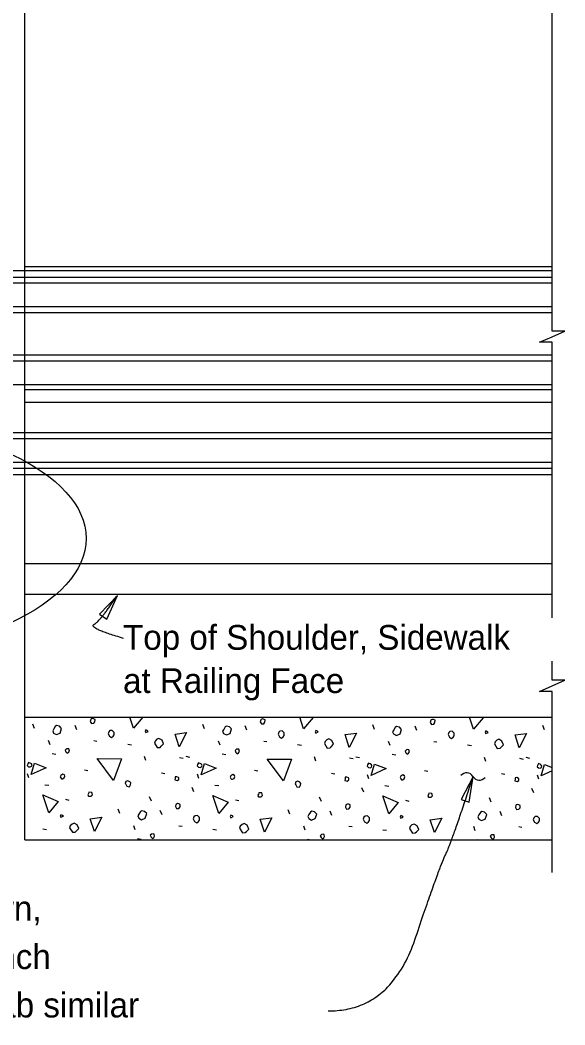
# Model space of a CAD drawing. Extents: x 120631.6 to 120706.2, y 120663.5 to 120716.4.
# Drawn here: x 120670.21 to 120674.64, y 120691.04 to 120699.22 of the extents above; entities that cross this region are included whole.
import ezdxf

# ---------------------------------------------------------------- set-up
doc = ezdxf.new("R2010")
doc.units = 0
for name, color, linetype in [('Dimension', 7, 'Continuous'), ('Miscellaneous', 7, 'Continuous'), ('SteelMisc_h', 7, 'Continuous'), ('TextStructures', 7, 'Continuous'), ('TrafBarrierConc', 7, 'Continuous')]:
    doc.layers.add(name, color=color, linetype=linetype)

msp = doc.modelspace()

# ---------------------------------------------------------------- linework, layer by layer
at = {"layer": 'Dimension'}
for points in [[(120674.5392, 120697.2127), (120674.5392, 120699.4757), (120674.4358, 120699.4757), (120674.5392, 120699.5207), (120674.6425, 120699.5657), (120674.5392, 120699.5657), (120674.5392, 120702.646)], [(120674.5392, 120695.9808), (120674.5392, 120696.597), (120674.4358, 120696.597), (120674.5392, 120696.642), (120674.6425, 120696.687), (120674.5392, 120696.687), (120674.5392, 120697.2127)], [(120674.5392, 120694.354), (120674.5392, 120695.9808)], [(120674.5392, 120692.2813), (120674.5392, 120693.7558), (120674.4358, 120693.7558), (120674.5392, 120693.8008), (120674.6425, 120693.8458), (120674.5392, 120693.8458), (120674.5392, 120694.0007)]]:
    msp.add_lwpolyline(points, dxfattribs=at)
for points in [[(120671.0028, 120694.5372), (120670.8585, 120694.383), (120670.9174, 120694.3441)], [(120673.8957, 120693.0627), (120673.7981, 120692.8754), (120673.8652, 120692.8537)]]:
    msp.add_lwpolyline(points, close=True, dxfattribs=at)
for centre, start, end in [((120673.8434, 120693.033), 30.00813, 141.73535), ((120673.9466, 120693.0926), 210.00813, 321.73535)]:
    msp.add_arc(centre, 0.0596, start, end, dxfattribs=at)
msp.add_ellipse((120668.6608, 120695.0005), major_axis=(2.0883, 0), ratio=0.464675, dxfattribs=at)
for points in [[(120671.0528, 120694.1873), (120670.7621, 120694.2707), (120670.8662, 120694.3306), (120671.0028, 120694.5372)], [(120672.7165, 120691.155), (120673.2263, 120691.1516), (120673.6239, 120692.3306), (120673.7232, 120692.5293), (120673.8957, 120693.0627)]]:
    msp.add_open_spline(points, degree=2, dxfattribs=at)
at = {"layer": 'Miscellaneous'}
for p, q in [((120670.3302, 120693.4537), (120670.3161, 120693.4891)), ((120671.7126, 120693.4502), (120671.6985, 120693.4855)), ((120673.095, 120693.4466), (120673.0809, 120693.482)), ((120670.6732, 120693.4431), (120670.659, 120693.4784)), ((120672.0556, 120693.4396), (120672.0414, 120693.4749)), ((120673.438, 120693.436), (120673.4238, 120693.4714)), ((120674.4774, 120693.4431), (120674.4633, 120693.4784)), ((120670.4557, 120693.3211), (120670.4434, 120693.3547)), ((120670.8111, 120693.3547), (120670.8358, 120693.3512)), ((120671.0868, 120693.3264), (120671.1169, 120693.3211)), ((120671.8381, 120693.3176), (120671.8258, 120693.3512)), ((120672.1934, 120693.3512), (120672.2182, 120693.3476)), ((120672.4692, 120693.3229), (120672.4993, 120693.3176)), ((120673.2205, 120693.314), (120673.2081, 120693.3476)), ((120673.5758, 120693.3476), (120673.6006, 120693.3441)), ((120673.8516, 120693.3194), (120673.8817, 120693.314)), ((120670.4734, 120693.2504), (120670.5035, 120693.2451)), ((120671.8558, 120693.2469), (120671.8859, 120693.2416)), ((120673.2382, 120693.2433), (120673.2683, 120693.238)), ((120671.2353, 120693.1921), (120671.2229, 120693.2257)), ((120671.5093, 120693.2186), (120671.5376, 120693.2115)), ((120671.5606, 120693.2274), (120671.5889, 120693.2204)), ((120672.6177, 120693.1885), (120672.6053, 120693.2221)), ((120672.8917, 120693.2151), (120672.92, 120693.208)), ((120672.943, 120693.2239), (120672.9713, 120693.2168)), ((120674.0001, 120693.185), (120673.9877, 120693.2186)), ((120674.2741, 120693.2115), (120674.3024, 120693.2044)), ((120674.3254, 120693.2204), (120674.3537, 120693.2133)), ((120670.2843, 120693.0507), (120670.2719, 120693.0842)), ((120670.7368, 120693.1178), (120670.7633, 120693.1125)), ((120671.3626, 120693.0931), (120671.3891, 120693.0878)), ((120671.6667, 120693.0471), (120671.6543, 120693.0807)), ((120672.1192, 120693.1143), (120672.1457, 120693.109)), ((120672.745, 120693.0895), (120672.7715, 120693.0842)), ((120673.049, 120693.0436), (120673.0367, 120693.0772)), ((120673.5016, 120693.1108), (120673.5281, 120693.1055)), ((120674.1274, 120693.086), (120674.1539, 120693.0807)), ((120674.4314, 120693.04), (120674.4191, 120693.0736)), ((120670.4133, 120692.9958), (120670.4451, 120692.9923)), ((120671.7957, 120692.9923), (120671.8275, 120692.9888)), ((120671.6242, 120692.9375), (120671.6101, 120692.9729)), ((120673.0066, 120692.934), (120672.9925, 120692.9693)), ((120673.1781, 120692.9888), (120673.2099, 120692.9852)), ((120674.389, 120692.9304), (120674.3749, 120692.9658)), ((120670.5812, 120692.8774), (120670.6095, 120692.8703)), ((120671.2795, 120692.8615), (120671.2654, 120692.8969)), ((120671.9636, 120692.8739), (120671.9919, 120692.8668)), ((120672.6619, 120692.858), (120672.6478, 120692.8933)), ((120673.346, 120692.8703), (120673.3743, 120692.8633)), ((120674.0443, 120692.8544), (120674.0302, 120692.8898)), ((120671.0232, 120692.7607), (120671.009, 120692.7961)), ((120671.3661, 120692.7501), (120671.352, 120692.7855)), ((120672.4056, 120692.7572), (120672.3914, 120692.7926)), ((120672.7485, 120692.7466), (120672.7344, 120692.7819)), ((120674.1309, 120692.7431), (120674.1168, 120692.7784)), ((120670.3974, 120692.637), (120670.4274, 120692.6317)), ((120671.1487, 120692.6282), (120671.1363, 120692.6617)), ((120671.504, 120692.6617), (120671.5288, 120692.6582)), ((120671.7798, 120692.6335), (120671.8098, 120692.6282)), ((120672.5311, 120692.6246), (120672.5187, 120692.6582)), ((120672.8864, 120692.6582), (120672.9112, 120692.6547)), ((120673.1622, 120692.6299), (120673.1922, 120692.6246)), ((120673.9135, 120692.6211), (120673.9011, 120692.6547)), ((120674.2688, 120692.6547), (120674.2936, 120692.6511)), ((120671.1664, 120692.5574), (120671.1964, 120692.5521)), ((120672.5488, 120692.5539), (120672.5788, 120692.5486)), ((120673.9312, 120692.5504), (120673.9558, 120692.546))]:
    msp.add_line(p, q, dxfattribs=at)
for points in [[(120670.7828, 120693.5103), (120670.7916, 120693.4944), (120670.8111, 120693.4961), (120670.8199, 120693.5085), (120670.8217, 120693.5279), (120670.8093, 120693.5333), (120670.8004, 120693.535), (120670.7898, 120693.5315), (120670.7863, 120693.5279), (120670.7828, 120693.5103)], [(120671.1346, 120693.4555), (120671.1051, 120693.546)], [(120671.2112, 120693.546), (120671.1346, 120693.4555)], [(120672.1652, 120693.5067), (120672.174, 120693.4908), (120672.1934, 120693.4926), (120672.2023, 120693.505), (120672.2041, 120693.5244), (120672.1917, 120693.5297), (120672.1828, 120693.5315), (120672.1722, 120693.5279), (120672.1687, 120693.5244), (120672.1652, 120693.5067)], [(120672.517, 120693.4519), (120672.4863, 120693.546)], [(120672.5898, 120693.546), (120672.5947, 120693.5439), (120672.517, 120693.4519)], [(120673.5476, 120693.5032), (120673.5564, 120693.4873), (120673.5758, 120693.4891), (120673.5847, 120693.5014), (120673.5864, 120693.5209), (120673.5741, 120693.5262), (120673.5652, 120693.5279), (120673.5546, 120693.5244), (120673.5511, 120693.5209), (120673.5476, 120693.5032)], [(120673.8993, 120693.4484), (120673.8676, 120693.546)], [(120673.9641, 120693.546), (120673.9771, 120693.5403), (120673.8993, 120693.4484)], [(120670.484, 120693.4166), (120670.507, 120693.4042), (120670.5371, 120693.4166), (120670.5494, 120693.4537), (120670.5317, 120693.4714), (120670.5088, 120693.4767), (120670.4982, 120693.4696), (120670.4858, 120693.4502), (120670.4769, 120693.4343), (120670.484, 120693.4166)], [(120670.9277, 120693.4113), (120670.9383, 120693.3901), (120670.956, 120693.3795), (120670.9702, 120693.3901), (120670.9772, 120693.4007), (120670.9772, 120693.4219), (120670.9613, 120693.4378), (120670.9419, 120693.436), (120670.933, 120693.4272), (120670.9277, 120693.4113)], [(120671.2336, 120693.4201), (120671.253, 120693.429), (120671.2459, 120693.436), (120671.2336, 120693.4413), (120671.2282, 120693.429), (120671.2336, 120693.4201)], [(120671.5058, 120693.3034), (120671.4722, 120693.4077), (120671.5659, 120693.4201), (120671.5058, 120693.3034)], [(120671.8664, 120693.413), (120671.8894, 120693.4007), (120671.9194, 120693.413), (120671.9318, 120693.4502), (120671.9141, 120693.4678), (120671.8912, 120693.4731), (120671.8806, 120693.4661), (120671.8682, 120693.4466), (120671.8593, 120693.4307), (120671.8664, 120693.413)], [(120672.3101, 120693.4077), (120672.3207, 120693.3865), (120672.3384, 120693.3759), (120672.3525, 120693.3865), (120672.3596, 120693.3971), (120672.3596, 120693.4183), (120672.3437, 120693.4343), (120672.3243, 120693.4325), (120672.3154, 120693.4236), (120672.3101, 120693.4077)], [(120672.6159, 120693.4166), (120672.6354, 120693.4254), (120672.6283, 120693.4325), (120672.6159, 120693.4378), (120672.6106, 120693.4254), (120672.6159, 120693.4166)], [(120672.8882, 120693.2999), (120672.8546, 120693.4042), (120672.9483, 120693.4166), (120672.8882, 120693.2999)], [(120673.2488, 120693.4095), (120673.2718, 120693.3971), (120673.3018, 120693.4095), (120673.3142, 120693.4466), (120673.2965, 120693.4643), (120673.2736, 120693.4696), (120673.2629, 120693.4625), (120673.2506, 120693.4431), (120673.2417, 120693.4272), (120673.2488, 120693.4095)], [(120673.6925, 120693.4042), (120673.7031, 120693.383), (120673.7208, 120693.3724), (120673.7349, 120693.383), (120673.742, 120693.3936), (120673.742, 120693.4148), (120673.7261, 120693.4307), (120673.7067, 120693.429), (120673.6978, 120693.4201), (120673.6925, 120693.4042)], [(120673.9983, 120693.413), (120674.0178, 120693.4219), (120674.0107, 120693.429), (120673.9983, 120693.4343), (120673.993, 120693.4219), (120673.9983, 120693.413)], [(120674.2706, 120693.2964), (120674.237, 120693.4007), (120674.3307, 120693.413), (120674.2706, 120693.2964)], [(120671.3043, 120693.3353), (120671.3272, 120693.2981), (120671.3502, 120693.2999), (120671.3591, 120693.3087), (120671.3785, 120693.3282), (120671.3661, 120693.3582), (120671.3414, 120693.3724), (120671.3237, 120693.3653), (120671.3096, 120693.3512), (120671.3043, 120693.3353)], [(120672.6867, 120693.3317), (120672.7096, 120693.2946), (120672.7326, 120693.2964), (120672.7415, 120693.3052), (120672.7609, 120693.3247), (120672.7485, 120693.3547), (120672.7238, 120693.3688), (120672.7061, 120693.3618), (120672.692, 120693.3476), (120672.6867, 120693.3317)], [(120674.069, 120693.3282), (120674.092, 120693.2911), (120674.115, 120693.2928), (120674.1239, 120693.3017), (120674.1433, 120693.3211), (120674.1309, 120693.3512), (120674.1062, 120693.3653), (120674.0885, 120693.3582), (120674.0744, 120693.3441), (120674.069, 120693.3282)], [(120670.5848, 120693.2628), (120670.5954, 120693.2522), (120670.606, 120693.2592), (120670.6131, 120693.2699), (120670.6095, 120693.2875), (120670.6007, 120693.2893), (120670.5883, 120693.2875), (120670.5777, 120693.2769), (120670.5848, 120693.2628)], [(120671.9672, 120693.2592), (120671.9778, 120693.2486), (120671.9884, 120693.2557), (120671.9955, 120693.2663), (120671.9919, 120693.284), (120671.9831, 120693.2858), (120671.9707, 120693.284), (120671.9601, 120693.2734), (120671.9672, 120693.2592)], [(120673.3496, 120693.2557), (120673.3602, 120693.2451), (120673.3708, 120693.2522), (120673.3779, 120693.2628), (120673.3743, 120693.2805), (120673.3655, 120693.2822), (120673.3531, 120693.2805), (120673.3425, 120693.2699), (120673.3496, 120693.2557)], [(120670.2807, 120693.1426), (120670.2931, 120693.1408), (120670.3055, 120693.1461), (120670.309, 120693.1567), (120670.3037, 120693.1656), (120670.2931, 120693.1726), (120670.2807, 120693.1779), (120670.2737, 120693.1638), (120670.2701, 120693.1532), (120670.2807, 120693.1426)], [(120670.3019, 120693.0789), (120670.3302, 120693.1709), (120670.4239, 120693.1337), (120670.3019, 120693.0789)], [(120670.9719, 120693.0312), (120670.8376, 120693.208), (120671.0373, 120693.2062), (120670.9719, 120693.0312)], [(120671.6631, 120693.139), (120671.6755, 120693.1373), (120671.6879, 120693.1426), (120671.6914, 120693.1532), (120671.6861, 120693.162), (120671.6755, 120693.1691), (120671.6631, 120693.1744), (120671.656, 120693.1603), (120671.6525, 120693.1496), (120671.6631, 120693.139)], [(120671.6843, 120693.0754), (120671.7126, 120693.1673), (120671.8063, 120693.1302), (120671.6843, 120693.0754)], [(120672.3543, 120693.0277), (120672.22, 120693.2044), (120672.4197, 120693.2027), (120672.3543, 120693.0277)], [(120673.0455, 120693.1355), (120673.0579, 120693.1337), (120673.0703, 120693.139), (120673.0738, 120693.1496), (120673.0685, 120693.1585), (120673.0579, 120693.1656), (120673.0455, 120693.1709), (120673.0384, 120693.1567), (120673.0349, 120693.1461), (120673.0455, 120693.1355)], [(120673.0667, 120693.0719), (120673.095, 120693.1638), (120673.1887, 120693.1267), (120673.0667, 120693.0719)], [(120674.4279, 120693.132), (120674.4403, 120693.1302), (120674.4527, 120693.1355), (120674.4562, 120693.1461), (120674.4509, 120693.1549), (120674.4403, 120693.162), (120674.4279, 120693.1673), (120674.4208, 120693.1532), (120674.4173, 120693.1426), (120674.4279, 120693.132)], [(120674.4491, 120693.0683), (120674.4774, 120693.1603), (120674.5392, 120693.1358)], [(120670.5494, 120693.0436), (120670.5565, 120693.0436), (120670.5706, 120693.0507), (120670.5759, 120693.0666), (120670.5742, 120693.0754), (120670.56, 120693.0825), (120670.5424, 120693.0719), (120670.5388, 120693.0613), (120670.5424, 120693.0507), (120670.5494, 120693.0436)], [(120671.9318, 120693.04), (120671.9389, 120693.04), (120671.953, 120693.0471), (120671.9583, 120693.063), (120671.9566, 120693.0719), (120671.9424, 120693.0789), (120671.9247, 120693.0683), (120671.9212, 120693.0577), (120671.9247, 120693.0471), (120671.9318, 120693.04)], [(120673.3142, 120693.0365), (120673.3213, 120693.0365), (120673.3354, 120693.0436), (120673.3407, 120693.0595), (120673.339, 120693.0683), (120673.3248, 120693.0754), (120673.3071, 120693.0648), (120673.3036, 120693.0542), (120673.3071, 120693.0436), (120673.3142, 120693.0365)], [(120674.5392, 120693.1088), (120674.4491, 120693.0683)], [(120671.0709, 120692.9994), (120671.0798, 120692.9835), (120671.101, 120692.9799), (120671.1098, 120692.9958), (120671.1133, 120693.01), (120671.1045, 120693.0188), (120671.0886, 120693.0277), (120671.0727, 120693.0224), (120671.0674, 120693.0065), (120671.0709, 120692.9994)], [(120671.4704, 120693.0347), (120671.4899, 120693.0294), (120671.5023, 120693.0383), (120671.504, 120693.0507), (120671.5005, 120693.0542), (120671.4863, 120693.0613), (120671.474, 120693.0595), (120671.4722, 120693.0471), (120671.4704, 120693.0347)], [(120672.4533, 120692.9958), (120672.4621, 120692.9799), (120672.4834, 120692.9764), (120672.4922, 120692.9923), (120672.4957, 120693.0065), (120672.4869, 120693.0153), (120672.471, 120693.0241), (120672.4551, 120693.0188), (120672.4498, 120693.0029), (120672.4533, 120692.9958)], [(120672.8528, 120693.0312), (120672.8723, 120693.0259), (120672.8846, 120693.0347), (120672.8864, 120693.0471), (120672.8829, 120693.0507), (120672.8687, 120693.0577), (120672.8564, 120693.056), (120672.8546, 120693.0436), (120672.8528, 120693.0312)], [(120674.2352, 120693.0277), (120674.2547, 120693.0224), (120674.267, 120693.0312), (120674.2688, 120693.0436), (120674.2653, 120693.0471), (120674.2511, 120693.0542), (120674.2388, 120693.0524), (120674.237, 120693.04), (120674.2352, 120693.0277)], [(120670.4451, 120692.766), (120670.3974, 120692.9128), (120670.5229, 120692.858), (120670.4451, 120692.766)], [(120670.7686, 120692.9022), (120670.7898, 120692.9022), (120670.8004, 120692.9128), (120670.7951, 120692.9322), (120670.7722, 120692.934), (120670.7686, 120692.9234), (120670.7633, 120692.9145), (120670.7686, 120692.9022), (120670.7651, 120692.9057)], [(120671.8275, 120692.7625), (120671.7798, 120692.9092), (120671.9053, 120692.8544), (120671.8275, 120692.7625)], [(120672.151, 120692.8986), (120672.1722, 120692.8986), (120672.1828, 120692.9092), (120672.1775, 120692.9287), (120672.1546, 120692.9304), (120672.151, 120692.9198), (120672.1457, 120692.911), (120672.151, 120692.8986), (120672.1475, 120692.9022)], [(120673.5334, 120692.8951), (120673.5546, 120692.8951), (120673.5652, 120692.9057), (120673.5599, 120692.9251), (120673.537, 120692.9269), (120673.5334, 120692.9163), (120673.5281, 120692.9075), (120673.5334, 120692.8951), (120673.5299, 120692.8986)], [(120671.4757, 120692.8173), (120671.4846, 120692.8014), (120671.504, 120692.8032), (120671.5129, 120692.8155), (120671.5146, 120692.835), (120671.5023, 120692.8403), (120671.4934, 120692.8421), (120671.4828, 120692.8385), (120671.4793, 120692.835), (120671.4757, 120692.8173)], [(120672.8581, 120692.8138), (120672.867, 120692.7979), (120672.8864, 120692.7996), (120672.8953, 120692.812), (120672.897, 120692.8314), (120672.8846, 120692.8368), (120672.8758, 120692.8385), (120672.8652, 120692.835), (120672.8617, 120692.8314), (120672.8581, 120692.8138)], [(120673.2099, 120692.759), (120673.1622, 120692.9057), (120673.2877, 120692.8509), (120673.2099, 120692.759)], [(120674.2405, 120692.8102), (120674.2494, 120692.7943), (120674.2688, 120692.7961), (120674.2776, 120692.8085), (120674.2794, 120692.8279), (120674.267, 120692.8332), (120674.2582, 120692.835), (120674.2476, 120692.8314), (120674.2441, 120692.8279), (120674.2405, 120692.8102)], [(120670.5441, 120692.7307), (120670.5636, 120692.7395), (120670.5565, 120692.7466), (120670.5441, 120692.7519), (120670.5388, 120692.7395), (120670.5441, 120692.7307)], [(120671.177, 120692.7236), (120671.2, 120692.7112), (120671.23, 120692.7236), (120671.2424, 120692.7607), (120671.2247, 120692.7784), (120671.2017, 120692.7837), (120671.1911, 120692.7766), (120671.1788, 120692.7572), (120671.1699, 120692.7413), (120671.177, 120692.7236)], [(120671.6207, 120692.7183), (120671.6313, 120692.6971), (120671.649, 120692.6865), (120671.6631, 120692.6971), (120671.6702, 120692.7077), (120671.6702, 120692.7289), (120671.6543, 120692.7448), (120671.6348, 120692.7431), (120671.626, 120692.7342), (120671.6207, 120692.7183)], [(120671.9265, 120692.7271), (120671.946, 120692.736), (120671.9389, 120692.7431), (120671.9265, 120692.7484), (120671.9212, 120692.736), (120671.9265, 120692.7271)], [(120672.5594, 120692.7201), (120672.5824, 120692.7077), (120672.6124, 120692.7201), (120672.6248, 120692.7572), (120672.6071, 120692.7749), (120672.5841, 120692.7802), (120672.5735, 120692.7731), (120672.5611, 120692.7537), (120672.5523, 120692.7378), (120672.5594, 120692.7201)], [(120673.3089, 120692.7236), (120673.3284, 120692.7325), (120673.3213, 120692.7395), (120673.3089, 120692.7448), (120673.3036, 120692.7325), (120673.3089, 120692.7236)], [(120673.9418, 120692.7165), (120673.9648, 120692.7042), (120673.9948, 120692.7165), (120674.0072, 120692.7537), (120673.9895, 120692.7713), (120673.9665, 120692.7766), (120673.9559, 120692.7696), (120673.9435, 120692.7501), (120673.9347, 120692.7342), (120673.9418, 120692.7165)], [(120670.6148, 120692.6458), (120670.6378, 120692.6087), (120670.6608, 120692.6105), (120670.6696, 120692.6193), (120670.6891, 120692.6388), (120670.6767, 120692.6688), (120670.652, 120692.683), (120670.6343, 120692.6759), (120670.6201, 120692.6617), (120670.6148, 120692.6458)], [(120670.8164, 120692.614), (120670.7828, 120692.7183), (120670.8765, 120692.7307), (120670.8164, 120692.614)], [(120671.9972, 120692.6423), (120672.0202, 120692.6052), (120672.0432, 120692.6069), (120672.052, 120692.6158), (120672.0715, 120692.6352), (120672.0591, 120692.6653), (120672.0344, 120692.6794), (120672.0167, 120692.6723), (120672.0025, 120692.6582), (120671.9972, 120692.6423)], [(120672.1988, 120692.6105), (120672.1652, 120692.7148), (120672.2589, 120692.7271), (120672.1988, 120692.6105)], [(120673.0031, 120692.7148), (120673.0137, 120692.6936), (120673.0314, 120692.683), (120673.0455, 120692.6936), (120673.0526, 120692.7042), (120673.0526, 120692.7254), (120673.0367, 120692.7413), (120673.0172, 120692.7395), (120673.0084, 120692.7307), (120673.0031, 120692.7148)], [(120673.3796, 120692.6388), (120673.4026, 120692.6016), (120673.4256, 120692.6034), (120673.4344, 120692.6122), (120673.4539, 120692.6317), (120673.4415, 120692.6617), (120673.4167, 120692.6759), (120673.3991, 120692.6688), (120673.3849, 120692.6547), (120673.3796, 120692.6388)], [(120673.5811, 120692.6069), (120673.5476, 120692.7112), (120673.6413, 120692.7236), (120673.5811, 120692.6069)], [(120674.3855, 120692.7112), (120674.3961, 120692.69), (120674.4138, 120692.6794), (120674.4279, 120692.69), (120674.435, 120692.7006), (120674.435, 120692.7218), (120674.4191, 120692.7378), (120674.3996, 120692.736), (120674.3908, 120692.7271), (120674.3855, 120692.7112)], [(120671.2777, 120692.5698), (120671.2884, 120692.5592), (120671.299, 120692.5663), (120671.306, 120692.5769), (120671.3025, 120692.5946), (120671.2937, 120692.5963), (120671.2813, 120692.5946), (120671.2707, 120692.584), (120671.2777, 120692.5698)], [(120672.6601, 120692.5663), (120672.6707, 120692.5557), (120672.6814, 120692.5627), (120672.6884, 120692.5734), (120672.6849, 120692.591), (120672.676, 120692.5928), (120672.6637, 120692.591), (120672.6531, 120692.5804), (120672.6601, 120692.5663)], [(120674.0425, 120692.5627), (120674.0531, 120692.5521), (120674.0637, 120692.5592), (120674.0708, 120692.5698), (120674.0673, 120692.5875), (120674.0584, 120692.5893), (120674.0461, 120692.5875), (120674.0355, 120692.5769), (120674.0425, 120692.5627)]]:
    msp.add_lwpolyline(points, dxfattribs=at)
at = {"layer": 'SteelMisc_h'}
for p, q in [((120654.8244, 120697.1805), (120674.5392, 120697.1805)), ((120655.4821, 120697.1283), (120674.5392, 120697.1283)), ((120655.4833, 120697.0801), (120674.5392, 120697.0801)), ((120655.0581, 120696.8873), (120674.5392, 120696.8873)), ((120655.4891, 120696.8391), (120674.5392, 120696.8391)), ((120655.4844, 120696.4469), (120674.5392, 120696.4469)), ((120655.4857, 120696.4951), (120674.5392, 120696.4951)), ((120655.4792, 120696.2541), (120674.5392, 120696.2541)), ((120655.4891, 120695.862), (120674.5392, 120695.862)), ((120655.488, 120695.8138), (120674.5392, 120695.8138)), ((120655.4817, 120695.6209), (120674.5392, 120695.6209)), ((120655.4828, 120695.5727), (120674.5392, 120695.5727)), ((120654.8244, 120695.5204), (120674.5392, 120695.5204))]:
    msp.add_line(p, q, dxfattribs=at)
at = {"layer": 'TrafBarrierConc'}
for p, q in [((120670.2503, 120692.5461), (120670.2503, 120702.4835)), ((120670.2503, 120697.2127), (120674.5392, 120697.2127)), ((120670.2503, 120696.2127), (120674.5392, 120696.2127)), ((120670.2503, 120696.1085), (120674.5392, 120696.1085)), ((120670.2503, 120694.796), (120674.5392, 120694.796)), ((120670.2503, 120694.5461), (120674.5392, 120694.5461)), ((120670.2503, 120693.546), (120674.5392, 120693.546)), ((120670.2503, 120692.546), (120674.5392, 120692.546))]:
    msp.add_line(p, q, dxfattribs=at)

# ---------------------------------------------------------------- texts
at = {"layer": 'Dimension'}
for s, p in [('Top of Shoulder, Sidewalk', (120671.0491, 120694.0943)), ('at Railing Face', (120671.0491, 120693.7423))]:
    msp.add_text(s, height=0.2016, dxfattribs=at).set_placement(p)
at = {"layer": 'TextStructures'}
for s, p in [('T-Shaped Spread Footing Shown, ', (120666.3103, 120691.8889)), ('L-Shaped Spread Footing , Trench ', (120666.3103, 120691.4953)), ('Footing Similar and Junction Slab similar', (120666.3103, 120691.1017))]:
    msp.add_text(s, height=0.2016, dxfattribs=at).set_placement(p)

doc.saveas('drawing.dxf')
